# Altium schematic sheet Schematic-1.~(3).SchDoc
size A4; SheetNumber: 1; SheetTotal: 1
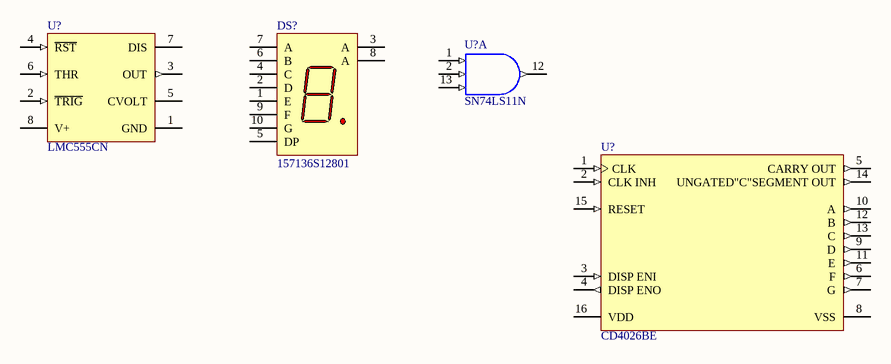
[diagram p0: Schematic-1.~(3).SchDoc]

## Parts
(Parts that share a designator on the sheet are numbered #1, #2 ... from top to bottom, then left to right.)
DS?  157136S12801  [WL-T7DS_L17.5W12.4H7]
U?#1  LMC555CN  [P0008A]
U?#2  SN74LS11N  [N0014A]  (part A of 4)
U?#3  CD4026BE  [N0016A]

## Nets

Not connected (* = marked no-connect by the designer): DS? 1(E) 2(D) 3(A) 4(C) 5(DP) 6(B) 7(A) 8(A) 9(F) 10(G); U?#1 1(GND) 2(~{TRIG}) 3(OUT) 4(~{RST}) 5(CVOLT) 6(THR) 7(DIS) 8(V+); U?#2 1(1A) 2(1B) 12(1Y) 13(1C); U?#3 1(CLK) 2(CLK_INH) 3(DISP_ENI) 4(DISP_ENO) 5(CARRY_OUT) 6(F) 7(G) 8(VSS) 9(D) 10(A) 11(E) 12(B) 13(C) 14(UNGATED"C"SEGMENT_OUT) 15(RESET) 16(VDD)

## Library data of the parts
DS? = CMP-03913-119893999-3: 7-Seg Display, Comm Anode, Super Red Rohs Compliant: Yes; Forward Voltage: 2V; Dominant Wavelength: 635nm; Max Reverse Voltage (DC): 5V; Forward Current: 100mA; Luminous Intensity: 20mcd
U?#1 = CMP-0056-00035-3: CMOS Timer, 8-pin MDIP; Manufacturer: Texas Instruments; PowerWise: N; CompType: Analog IC; PackageTopMarking: NSUZXYTTE#*LMC*555CN
U?#2 = CMP-0777-00254-3: Triple 3-input positive-AND gates, N0014A, TUBE; Manufacturer: Texas Instruments; Output Type: TTL; VCC(Min)(V): 4.75; Technology Family: LS; Bits(#): 3; Voltage(Nom)(V): 5; ICC @ Nom Voltage(Max)(mA): 0.0036; Rating: Catalog; VCC(Max)(V): 5.25; tpd @ Nom Voltage(Max)(ns): 15; Output Drive (IOL/IOH)(Max)(mA): 0/8; F @ Nom Voltage(Max)(Mhz): 35; Schmitt Trigger: No
U?#3 = CMP-1623-00561-2: CMOS Decade Counter/Divider with Decoded 7-Segment Display Outputs and Display Enable, N0016A, TUBE; Manufacturer: Texas Instruments; ICC @ Nom Voltage(Max)(mA): 0.03; tpd @ Nom Voltage(Max)(ns): 250; F @ Nom Voltage(Max)(Mhz): 8; Bits(#): 7; VCC(Max)(V): 18; VCC(Min)(V): 3; Output Drive (IOL/IOH)(Max)(mA): 1.5/-1.5; Inputs: 1; Rating: Catalog; Technology Family: CD4000; Schmitt Trigger: No; Voltage(Nom)(V): 5,10,15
